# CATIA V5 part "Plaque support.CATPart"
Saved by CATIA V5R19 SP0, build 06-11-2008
Part number: Pièce1
Bounding box of the stored display mesh (mm): x 0 to 50, y 0 to 390, z 0 to 330
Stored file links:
  C:\Users\Hicham57\Desktop\Chassis presse\Plaque support.CATPart
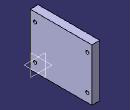
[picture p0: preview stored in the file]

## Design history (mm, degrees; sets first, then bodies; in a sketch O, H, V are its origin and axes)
Body1 (main body)
  Sketch1 on yz-plane, origin (0, 0, 0), H (0, 1, 0), V (0, 0, 1)
    line L1 (0, 0) -> (390, 0)
    line L2 (390, 0) -> (390, 330)
    line L3 (390, 330) -> (0, 330)
    line L4 (0, 330) -> (0, 0)
    length L1 = 390
    length L4 = 330
    horizontal: L1 H, L3 H
    vertical: L2 V, L4 V
  Pad1: profile Sketch1, direction (1, 0, 0), length 50
  Sketch2 on end face of Pad1, origin (50, 0, 0), H (0, 1, 0), V (0, 0, 1)
    circle A1 centre (360, 275) radius 10
    point P1 (360, 275)
    circle A2 centre (360, 55) radius 10
    point P2 (360, 55)
    circle A3 centre (30, 275) radius 10
    point P3 (30, 275)
    circle A4 centre (30, 55) radius 10
    point P4 (30, 55)
    reference projected line E1 (390, 330) -> (0, 330) from edge [face of Pad1 from Sketch1.L3 | end face of Pad1]
    reference projected line E2 (390, 0) -> (390, 330) from edge [face of Pad1 from Sketch1.L2 | end face of Pad1]
    reference projected line E3 (390, 0) -> (390, 330) from edge [face of Pad1 from Sketch1.L2 | end face of Pad1]
    reference projected line E4 (0, 0) -> (390, 0) from edge [face of Pad1 from Sketch1.L1 | end face of Pad1]
    reference projected line E5 (0, 330) -> (0, 0) from edge [face of Pad1 from Sketch1.L4 | end face of Pad1]
    reference projected line E6 (0, 330) -> (0, 0) from edge [face of Pad1 from Sketch1.L4 | end face of Pad1]
    reference projected line E7 (390, 330) -> (0, 330) from edge [face of Pad1 from Sketch1.L3 | end face of Pad1]
    reference projected line E8 (0, 0) -> (390, 0) from edge [face of Pad1 from Sketch1.L1 | end face of Pad1]
    radius A1 = 10
    radius A2 = 10
    radius A4 = 10
    radius A3 = 10
    distance P1 E1 = 55
    distance P1 E2 = 30
    distance P2 E3 = 30
    distance P2 E4 = 55
    distance P3 E5 = 30
    distance P4 E6 = 30
    distance P3 E7 = 55
    distance P4 E8 = 55
  Pocket1: profile Sketch2, direction (-1, 0, 0), length 50
  Thread1: diameter 22, depth 50, pitch 1, on face of Pocket1 from Sketch2.A3, from start face of Pad1
  Thread2: diameter 22, depth 50, pitch 1, on face of Pocket1 from Sketch2.A4, from start face of Pad1
  Thread3: diameter 22, depth 50, pitch 1, on face of Pocket1 from Sketch2.A2, from start face of Pad1
  Thread4: diameter 22, depth 50, pitch 1, on face of Pocket1 from Sketch2.A1, from start face of Pad1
